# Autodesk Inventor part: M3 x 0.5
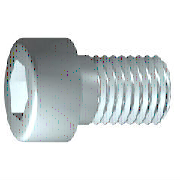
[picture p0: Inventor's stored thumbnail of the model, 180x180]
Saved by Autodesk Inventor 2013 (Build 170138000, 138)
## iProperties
IsCustomPart: 0
Created: 2015-10
Part Number: M3 x 0.5
Material: 강, 연강
Description: 6각머리 태핑 나사
Document SubType Name: Modeling
Standard: KS B 1003
Designer: mdu
Standards Organization: KS
Language: ko-KR
Size Designation: M 3 x 12
Categories: <MemberInstance><Categories><Category DisplayName="조임쇠" InternalName="e4da775c-781d-43d5-af7c-5136215cf5a6" Mnemonic="FSTN"><Category DisplayName="볼트" InternalN
Density: 1 g/cm^3
Author: mdu
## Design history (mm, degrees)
sketch "스케치1"
  geometry: L1 (-0.867, 0)-(12, 0); L2 (12, 0)-(12, 1.5); L3 (12, 1.5)-(1.25, 1.5); L4 (1.25, 1.5)-(0.943, 1.5); L5 (0.943, 1.5)-(0, 1.5); L6 (0, 1.5)-(0, 2.75); L7 (0, 2.75)-(-3, 2.75); L8 (-3, 2.75)-(-3, 1.443); L9 (-3, 1.443)-(-1.7, 1.443); L10 (-1.7, 1.443)-(-0.867, 0); L11 (-6, 0)-(15, 0) reference; L12 (0, -0.55)-(0, 3.3) reference; L13 (1.25, 1.5)-(0, 1.5)
  constraints: 22 end point, 6 parallel, 2 collinear, 2 perpendicular, 1 horizontal, 1 point on line
  dimensions: "d1" = 10.75 distance from line of L3.end L2 (= GEL); "d2" = 0.30683 distance of L4.end L3.end (computed from GAL); "d3" = 3 distance between parallel lines of L8 L6 (= KOH); "d4" = 1.3 distance of L8.end L9.end (= INTI); "d5" = 60 deg angle of L10 L1; "d6" = 3 diameter of L3 L1 (= GD); "d7" = 3 diameter of L5 L1 (= BDM); "d8" = 2.88675 diameter of L9 L1 (= 1.1547 x SW); "d9" = 5.5 diameter of L7 L1 (= KOD); "d26" = 12 distance between parallel lines of L12 L2 (= NLG)
revolve "본체" sketch "스케치1" stored, may be unused: angle "d10" = 90 deg
sketch "스케치2"
  geometry: L1 (0, -3.85)-(0, 3.85) reference; L2 (-3.85, 0)-(3.85, 0) reference; L3 (1.443, 0)-(0.722, -1.25); L4 (0.722, -1.25)-(-0.722, -1.25); L5 (-0.722, -1.25)-(-1.443, 0); L6 (-1.443, 0)-(-0.722, 1.25); L7 (-0.722, 1.25)-(0.722, 1.25); L8 (0.722, 1.25)-(1.443, 0); 2 further points
  constraints: 12 end point, 1 coincident, 1 horizontal alignment, 1 point on line, 12 other
extrude "슬롯" join sketch "스케치2" stored distance "d11" = 10; taper "d12" = 0 deg
workplane "Work Plane1"
fillet "Fillet2" dims "d30" = 0.1 (= R)
body "Solid1"
fillet "모깎기1" dims "d17" = 0.3 (= RR)
feature "스레드" dims "d13" = 10.75 (= GEL), "d14" = 0
chamfer "모따기1" distance "d15" = 0.30673 (= -0.5 x SPD + 0.5 x GD); stored, may be unused: second distance "d16" = 0.30673 (= GUL), angle "d27" = 45 deg
other parameters: "GD" = 3 (= NND) [user parameter; used in 2 equation terms], "NLG" = 12 [user parameter; used in 1 equation term], "GEL" = 10.75 [user parameter; used in 2 equation terms], "KOD" = 5.5 [user parameter; used in 1 equation term], "KOH" = 3 [user parameter; used in 1 equation term], "INTI" = 1.3 [user parameter; used in 1 equation term], "GAL" = 0.30673 (= 0.61345 x PTC) [user parameter; used in 1 equation term], "GUL" = 0.30673 (= 0.61345 x PTC) [user parameter; used in 1 equation term], "BDM" = 3 (= NND) [user parameter; used in 1 equation term], "SW" = 2.5 [user parameter; used in 2 equation terms], "RR" = 0.3 [user parameter; used in 1 equation term], "SPD" = 2.38655 (= NND - 1.2269 x PTC) [user parameter; used in 1 equation term], "d19" = 0, "d28" = 0, "d29" = 0, "R" = 0.1 [user parameter; used in 1 equation term], "PHH" = 0.1 [user parameter], "GD1" = 2.38655 (= THREADDIA - 1.2269 x PTC) [user parameter], "THREADDIA" = 3 [user parameter; used in 1 equation term], "FAWI" = 45 deg [user parameter], "PTC" = 0.5 [user parameter; used in 5 equation terms], "NND" = 3 [user parameter; used in 3 equation terms], "TOA" = 30 deg [user parameter], "E0" = 2.8875 (= 1.155 x SW) [user parameter]
